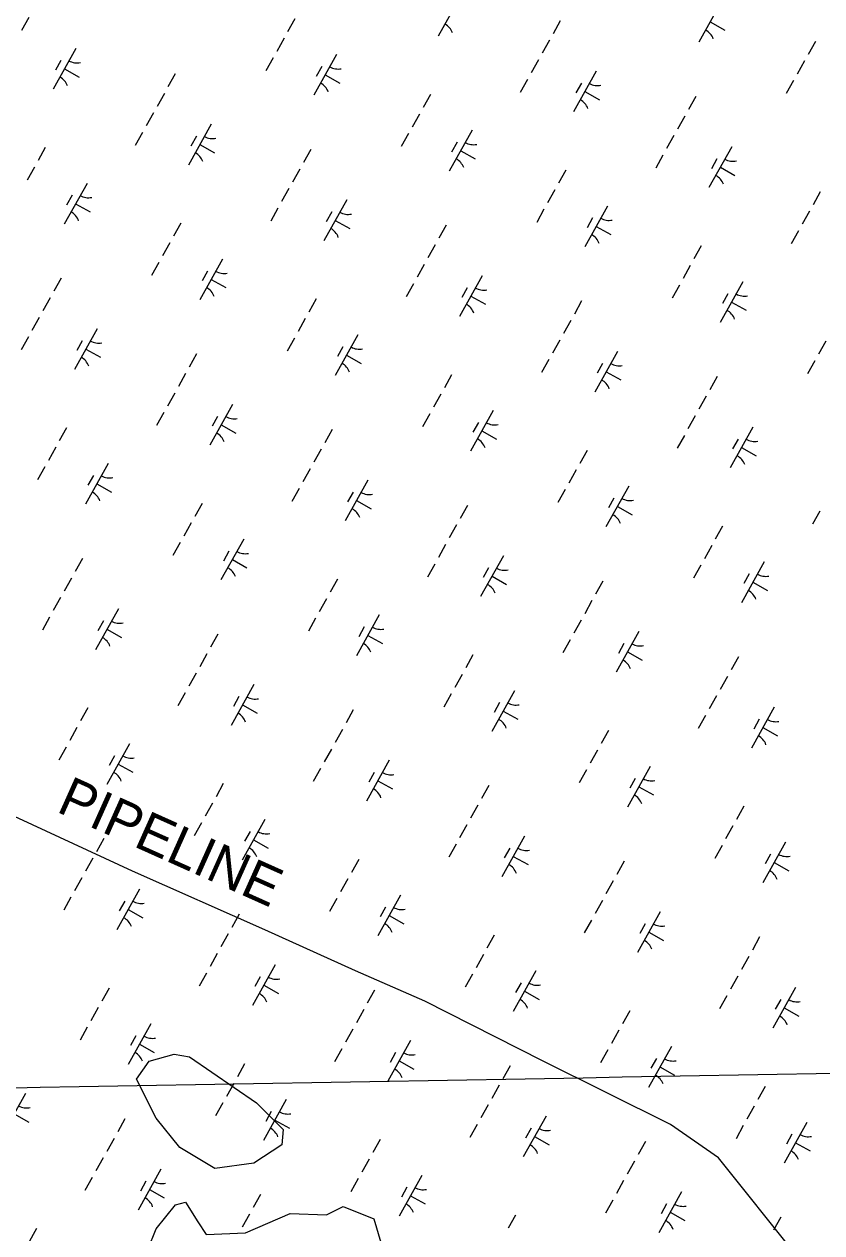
# Model space of a CAD drawing. Extents: x 3923531 to 3943530, y 207391 to 229799.
# Drawn here: x 3930894 to 3931749, y 217762 to 219057 of the extents above; entities that cross this region are included whole.
import ezdxf

# ---------------------------------------------------------------- set-up
doc = ezdxf.new("R2010")
doc.units = 0
for name, color, linetype in [('V-GRID-MAJR', 7, 'Continuous'), ('V-SITE-VEGE', 7, 'Continuous'), ('V-UTIL-IDEN', 7, 'Continuous'), ('V-UTIL-LINE', 7, 'Continuous'), ('V-WETL-SWMP', 7, 'Continuous')]:
    doc.layers.add(name, color=color, linetype=linetype)

msp = doc.modelspace()

# ---------------------------------------------------------------- linework, layer by layer
at = {"layer": 'V-GRID-MAJR'}
msp.add_spline([(3929435.5, 217891.9), (3930329.2, 217907.7), (3935652.4, 218002.6), (3939803.5, 218077.1)], degree=3, dxfattribs=at)
at = {"layer": 'V-SITE-VEGE'}
for points in [[(3931171.8, 217872.8), (3931170.3, 217856.3), (3931140.4, 217836.9), (3931098.5, 217830.9), (3931061.1, 217853.4), (3931035.6, 217884.8), (3931014.7, 217926.7), (3931028.2, 217946.2), (3931055.1, 217953.6), (3931071.6, 217950.6), (3931143.4, 217901.3)], [(3931179.3, 217783), (3931218.2, 217781.5), (3931236.1, 217790.5), (3931269, 217777), (3931276.5, 217751.6), (3931257.1, 217721.6), (3931239.1, 217693.2), (3931213.7, 217672.2), (3931176.3, 217663.3), (3931152.3, 217615.4), (3931116.4, 217598.9), (3931083.5, 217630.3), (3931055.1, 217673.7), (3931064.1, 217685.7), (3931089.5, 217690.2), (3931082, 217720.1), (3931041.6, 217723.1), (3931026.7, 217744.1), (3931035.6, 217766.5), (3931056.6, 217792), (3931067.1, 217795), (3931080.5, 217774), (3931089.5, 217760.5), (3931131.4, 217762)]]:
    msp.add_lwpolyline(points, close=True, dxfattribs=at)
at = {"layer": 'V-UTIL-LINE'}
msp.add_lwpolyline([(3931722.7, 217737.3), (3931638.5, 217842.4), (3931587.2, 217878.3), (3931450.1, 217946.4), (3931323.8, 218010.3), (3931249.5, 218042.8), (3931152.1, 218086.6), (3931010.3, 218149.6), (3930854.2, 218221.7), (3930697.7, 218316.3), (3930484, 218439.5), (3930190.1, 218598.9), (3929976.7, 218714), (3929898, 218757.3)], dxfattribs=at)
at = {"layer": 'V-WETL-SWMP'}
for p, q in [((3931362.4, 219087.9), (3931338, 219044.2)), ((3931642, 219081.4), (3931617.6, 219037.7)), ((3930899.3, 219064.2), (3930891.5, 219050.2)), ((3931184.5, 219062.9), (3931176.7, 219048.9)), ((3931469, 219060.8), (3931461.2, 219046.9)), ((3931629.8, 219059.6), (3931645.5, 219050.8)), ((3931172.8, 219042), (3931165, 219028)), ((3931457.3, 219039.9), (3931449.5, 219025.9)), ((3930949.6, 219031), (3930925.2, 218987.4)), ((3931742.5, 219038.6), (3931734.7, 219024.6)), ((3930933.6, 219018.2), (3930927.7, 219007.7)), ((3931161.1, 219021), (3931153.3, 219007)), ((3931229.2, 219024.5), (3931204.8, 218980.9)), ((3931445.6, 219018.9), (3931437.8, 219004.9)), ((3931730.8, 219017.7), (3931723, 219003.7)), ((3930937.4, 219009.2), (3930953.1, 219000.4)), ((3931056.2, 219004), (3931048.4, 218990)), ((3931213.2, 219011.7), (3931207.3, 219001.2)), ((3931217, 219002.7), (3931232.7, 218993.9)), ((3931507.6, 219006.7), (3931483.2, 218963.1)), ((3931433.9, 218998), (3931426.1, 218984)), ((3931491.6, 218993.9), (3931485.7, 218983.4)), ((3931719.1, 218996.7), (3931711.3, 218982.7)), ((3931044.5, 218983), (3931036.7, 218969.1)), ((3931329.7, 218981.8), (3931321.9, 218967.8)), ((3931495.4, 218984.9), (3931511.1, 218976.1)), ((3931614.3, 218979.7), (3931606.5, 218965.7)), ((3931032.8, 218962.1), (3931025, 218948.1)), ((3931094.8, 218949.9), (3931070.4, 218906.2)), ((3931318, 218960.8), (3931310.2, 218946.9)), ((3931602.6, 218958.7), (3931594.7, 218944.8)), ((3931021.1, 218941.1), (3931013.3, 218927.2)), ((3931078.8, 218937.1), (3931072.9, 218926.6)), ((3931306.3, 218939.9), (3931298.5, 218925.9)), ((3931374.4, 218943.4), (3931350, 218899.8)), ((3931590.8, 218937.8), (3931583, 218923.8)), ((3930916.9, 218924.9), (3930909.1, 218911)), ((3931082.6, 218928.1), (3931098.3, 218919.3)), ((3931358.4, 218930.6), (3931352.5, 218920.1)), ((3931652.8, 218925.6), (3931628.4, 218882)), ((3931201.4, 218922.9), (3931193.6, 218908.9)), ((3931362.2, 218921.6), (3931377.9, 218912.8)), ((3931579.1, 218916.8), (3931571.3, 218902.9)), ((3931636.8, 218912.8), (3931631, 218902.3)), ((3930905.2, 218904), (3930897.4, 218890)), ((3931189.7, 218901.9), (3931181.9, 218887.9)), ((3931474.9, 218900.7), (3931467.1, 218886.7)), ((3931640.6, 218903.8), (3931656.3, 218895)), ((3930961.6, 218886.6), (3930937.2, 218842.9)), ((3930945.6, 218873.8), (3930939.7, 218863.3)), ((3931178, 218881), (3931170.2, 218867)), ((3931463.2, 218879.7), (3931455.4, 218865.7)), ((3931747.8, 218877.6), (3931740, 218863.7)), ((3930949.4, 218864.8), (3930965.1, 218856)), ((3931166.3, 218860), (3931158.5, 218846)), ((3931240, 218868.8), (3931215.6, 218825.1)), ((3931451.5, 218858.8), (3931443.7, 218844.8)), ((3931519.6, 218862.3), (3931495.2, 218818.6)), ((3931224, 218855.9), (3931218.1, 218845.5)), ((3931227.8, 218846.9), (3931243.5, 218838.2)), ((3931503.6, 218849.5), (3931497.8, 218839)), ((3931736.1, 218856.7), (3931728.3, 218842.7)), ((3931062.1, 218843.8), (3931054.3, 218829.9)), ((3931346.6, 218841.7), (3931338.8, 218827.8)), ((3931507.4, 218840.5), (3931523.1, 218831.7)), ((3931724.4, 218835.7), (3931716.6, 218821.7)), ((3931050.4, 218822.9), (3931042.6, 218808.9)), ((3931334.9, 218820.8), (3931327.1, 218806.8)), ((3931620.1, 218819.5), (3931612.3, 218805.6)), ((3931038.7, 218801.9), (3931030.9, 218787.9)), ((3931106.8, 218805.5), (3931082.4, 218761.8)), ((3931323.2, 218799.8), (3931315.4, 218785.9)), ((3931608.4, 218798.6), (3931600.6, 218784.6)), ((3930933.8, 218784.9), (3930926, 218770.9)), ((3931090.8, 218792.6), (3931084.9, 218782.2)), ((3931094.6, 218783.6), (3931110.3, 218774.9)), ((3931385.2, 218787.6), (3931360.8, 218744)), ((3931664.8, 218781.2), (3931640.4, 218737.5)), ((3931311.5, 218778.9), (3931303.7, 218764.9)), ((3931369.2, 218774.8), (3931363.3, 218764.3)), ((3931596.7, 218777.6), (3931588.9, 218763.7)), ((3931648.8, 218768.3), (3931643, 218757.9)), ((3930922.1, 218763.9), (3930914.3, 218750)), ((3931207.3, 218762.7), (3931199.5, 218748.7)), ((3931373, 218765.8), (3931388.7, 218757)), ((3931491.9, 218760.6), (3931484.1, 218746.6)), ((3931652.6, 218759.3), (3931668.3, 218750.6)), ((3930910.4, 218743), (3930902.6, 218729)), ((3931195.6, 218741.7), (3931187.8, 218727.8)), ((3930972.4, 218730.8), (3930948, 218687.2)), ((3931480.2, 218739.7), (3931472.4, 218725.7)), ((3930898.7, 218722), (3930890.9, 218708.1)), ((3930956.4, 218718), (3930950.5, 218707.5)), ((3931183.9, 218720.8), (3931176.1, 218706.8)), ((3931252, 218724.3), (3931227.6, 218680.7)), ((3931468.5, 218718.7), (3931460.7, 218704.7)), ((3931753.6, 218717.5), (3931745.8, 218703.5)), ((3930960.2, 218709), (3930975.9, 218700.2)), ((3931079, 218703.8), (3931071.2, 218689.8)), ((3931236, 218711.5), (3931230.1, 218701)), ((3931530.4, 218706.5), (3931506, 218662.9)), ((3931239.8, 218702.5), (3931255.5, 218693.7)), ((3931456.7, 218697.8), (3931448.9, 218683.8)), ((3931514.4, 218693.7), (3931508.6, 218683.2)), ((3931741.9, 218696.5), (3931734.1, 218682.5)), ((3931067.3, 218682.8), (3931059.5, 218668.9)), ((3931352.5, 218681.6), (3931344.7, 218667.6)), ((3931518.2, 218684.7), (3931533.9, 218675.9)), ((3931637.1, 218679.5), (3931629.3, 218665.5)), ((3931055.6, 218661.9), (3931047.8, 218647.9)), ((3931340.8, 218660.6), (3931333, 218646.7)), ((3931625.4, 218658.5), (3931617.6, 218644.6)), ((3931043.9, 218640.9), (3931036.1, 218627)), ((3931117.6, 218649.7), (3931093.2, 218606)), ((3931329.1, 218639.7), (3931321.3, 218625.7)), ((3931397.2, 218643.2), (3931372.8, 218599.6)), ((3931101.6, 218636.9), (3931095.7, 218626.4)), ((3931105.4, 218627.9), (3931121.1, 218619.1)), ((3931381.2, 218630.4), (3931375.4, 218619.9)), ((3931613.7, 218637.6), (3931605.9, 218623.6)), ((3931675.6, 218625.4), (3931651.2, 218581.7)), ((3930939.7, 218624.7), (3930931.9, 218610.8)), ((3931224.3, 218622.7), (3931216.5, 218608.7)), ((3931385, 218621.4), (3931400.7, 218612.6)), ((3931602, 218616.6), (3931594.2, 218602.7)), ((3931659.6, 218612.6), (3931653.8, 218602.1)), ((3930928, 218603.8), (3930920.2, 218589.8)), ((3931212.6, 218601.7), (3931204.7, 218587.7)), ((3931497.7, 218600.4), (3931489.9, 218586.5)), ((3931663.4, 218603.6), (3931679.1, 218594.8)), ((3930984.4, 218586.4), (3930960, 218542.7)), ((3930916.3, 218582.8), (3930908.5, 218568.9)), ((3930968.4, 218573.5), (3930962.5, 218563.1)), ((3931200.8, 218580.7), (3931193, 218566.8)), ((3931486, 218579.5), (3931478.2, 218565.5)), ((3930972.2, 218564.5), (3930987.9, 218555.8)), ((3931262.8, 218568.6), (3931238.4, 218524.9)), ((3931542.4, 218562.1), (3931518, 218518.4)), ((3931189.1, 218559.8), (3931181.3, 218545.8)), ((3931246.8, 218555.7), (3931241, 218545.3)), ((3931474.3, 218558.5), (3931466.5, 218544.6)), ((3931526.4, 218549.3), (3931520.6, 218538.8)), ((3931084.9, 218543.6), (3931077.1, 218529.6)), ((3931250.6, 218546.7), (3931266.3, 218538)), ((3931369.5, 218541.5), (3931361.7, 218527.6)), ((3931530.2, 218540.3), (3931545.9, 218531.5)), ((3931747.2, 218535.5), (3931739.4, 218521.5)), ((3931073.2, 218522.7), (3931065.4, 218508.7)), ((3931357.8, 218520.6), (3931350, 218506.6)), ((3931643, 218519.3), (3931635.2, 218505.4)), ((3931061.5, 218501.7), (3931053.7, 218487.7)), ((3931129.6, 218505.2), (3931105.2, 218461.6)), ((3931346.1, 218499.6), (3931338.3, 218485.7)), ((3931631.3, 218498.4), (3931623.5, 218484.4)), ((3930956.7, 218484.7), (3930948.8, 218470.7)), ((3931113.6, 218492.4), (3931107.8, 218481.9)), ((3931117.4, 218483.4), (3931133.1, 218474.6)), ((3931408, 218487.4), (3931383.6, 218443.8)), ((3931334.4, 218478.7), (3931326.6, 218464.7)), ((3931392, 218474.6), (3931386.2, 218464.1)), ((3931619.6, 218477.4), (3931611.7, 218463.5)), ((3931687.6, 218481), (3931663.3, 218437.3)), ((3930944.9, 218463.7), (3930937.1, 218449.8)), ((3931230.1, 218462.5), (3931222.3, 218448.5)), ((3931395.8, 218465.6), (3931411.5, 218456.8)), ((3931514.7, 218460.4), (3931506.9, 218446.4)), ((3931671.6, 218468.1), (3931665.8, 218457.7)), ((3931675.4, 218459.1), (3931691.2, 218450.4)), ((3930933.2, 218442.8), (3930925.4, 218428.8)), ((3931218.4, 218441.5), (3931210.6, 218427.6)), ((3931503, 218439.5), (3931495.2, 218425.5)), ((3930921.5, 218421.8), (3930913.7, 218407.9)), ((3930995.2, 218430.6), (3930970.8, 218386.9)), ((3931206.7, 218420.6), (3931198.9, 218406.6)), ((3931274.8, 218424.1), (3931250.4, 218380.5)), ((3931491.3, 218418.5), (3931483.5, 218404.5)), ((3930979.2, 218417.8), (3930973.3, 218407.3)), ((3930983, 218408.8), (3930998.7, 218400)), ((3931258.8, 218411.3), (3931253, 218400.8)), ((3931553.2, 218406.3), (3931528.8, 218362.7)), ((3931101.9, 218403.6), (3931094.1, 218389.6)), ((3931262.6, 218402.3), (3931278.3, 218393.5)), ((3931479.6, 218397.5), (3931471.8, 218383.6)), ((3931537.2, 218393.5), (3931531.4, 218383)), ((3931090.2, 218382.6), (3931082.4, 218368.6)), ((3931375.4, 218381.4), (3931367.6, 218367.4)), ((3931541, 218384.5), (3931556.8, 218375.7)), ((3931659.9, 218379.3), (3931652.1, 218365.3)), ((3931078.5, 218361.7), (3931070.7, 218347.7)), ((3931363.7, 218360.4), (3931355.8, 218346.4)), ((3931648.2, 218358.3), (3931640.4, 218344.4)), ((3931066.7, 218340.7), (3931058.9, 218326.7)), ((3931140.4, 218349.5), (3931116, 218305.8)), ((3931420, 218343), (3931395.6, 218299.3)), ((3931124.4, 218336.7), (3931118.6, 218326.2)), ((3931128.2, 218327.7), (3931143.9, 218318.9)), ((3931351.9, 218339.5), (3931344.1, 218325.5)), ((3931404, 218330.2), (3931398.2, 218319.7)), ((3931636.5, 218337.4), (3931628.7, 218323.4)), ((3930962.5, 218324.5), (3930954.7, 218310.6)), ((3931247.1, 218322.4), (3931239.3, 218308.5)), ((3931407.8, 218321.2), (3931423.6, 218312.4)), ((3931624.8, 218316.4), (3931617, 218302.5)), ((3931698.4, 218325.2), (3931674.1, 218281.5)), ((3930950.8, 218303.6), (3930943, 218289.6)), ((3931235.4, 218301.5), (3931227.6, 218287.5)), ((3931682.4, 218312.4), (3931676.6, 218301.9)), ((3931686.3, 218303.4), (3931702, 218294.6)), ((3931520.6, 218300.2), (3931512.8, 218286.3)), ((3930939.1, 218282.6), (3930931.3, 218268.7)), ((3931007.2, 218286.2), (3930982.8, 218242.5)), ((3931223.7, 218280.5), (3931215.9, 218266.6)), ((3931508.9, 218279.3), (3931501.1, 218265.3)), ((3930991.2, 218273.3), (3930985.4, 218262.9)), ((3930995, 218264.3), (3931010.7, 218255.6)), ((3931285.6, 218268.4), (3931261.2, 218224.7)), ((3931212, 218259.6), (3931204.2, 218245.6)), ((3931269.6, 218255.5), (3931263.8, 218245.1)), ((3931497.2, 218258.3), (3931489.4, 218244.4)), ((3931565.2, 218261.9), (3931540.9, 218218.2)), ((3931107.7, 218243.4), (3931099.9, 218229.4)), ((3931273.4, 218246.5), (3931289.1, 218237.7)), ((3931392.3, 218241.3), (3931384.5, 218227.4)), ((3931549.2, 218249), (3931543.4, 218238.6)), ((3931553.1, 218240), (3931568.8, 218231.3)), ((3931096, 218222.5), (3931088.2, 218208.5)), ((3931380.6, 218220.4), (3931372.8, 218206.4)), ((3931665.8, 218219.1), (3931658, 218205.1)), ((3931084.3, 218201.5), (3931076.5, 218187.5)), ((3931152.4, 218205), (3931128, 218161.4)), ((3931368.9, 218199.4), (3931361.1, 218185.4)), ((3931654.1, 218198.2), (3931646.3, 218184.2)), ((3931136.4, 218192.2), (3931130.6, 218181.7)), ((3931430.8, 218187.2), (3931406.5, 218143.6)), ((3930979.5, 218184.5), (3930971.7, 218170.5)), ((3931140.2, 218183.2), (3931155.9, 218174.4)), ((3931357.2, 218178.5), (3931349.4, 218164.5)), ((3931414.8, 218174.4), (3931409, 218163.9)), ((3931642.4, 218177.2), (3931634.6, 218163.2)), ((3931710.5, 218180.7), (3931686.1, 218137.1)), ((3930967.8, 218163.5), (3930960, 218149.6)), ((3931253, 218162.3), (3931245.2, 218148.3)), ((3931418.6, 218165.4), (3931434.4, 218156.6)), ((3931537.5, 218160.2), (3931529.7, 218146.2)), ((3931694.5, 218167.9), (3931688.6, 218157.4)), ((3931698.3, 218158.9), (3931714, 218150.1)), ((3930956.1, 218142.6), (3930948.3, 218128.6)), ((3931241.3, 218141.3), (3931233.5, 218127.4)), ((3931525.8, 218139.2), (3931518, 218125.3)), ((3930944.4, 218121.6), (3930936.6, 218107.7)), ((3931018, 218130.4), (3930993.6, 218086.7)), ((3931229.6, 218120.4), (3931221.7, 218106.4)), ((3931297.6, 218123.9), (3931273.3, 218080.3)), ((3931002, 218117.6), (3930996.2, 218107.1)), ((3931005.8, 218108.6), (3931021.5, 218099.8)), ((3931281.6, 218111.1), (3931275.8, 218100.6)), ((3931514.1, 218118.3), (3931506.3, 218104.3)), ((3931124.7, 218103.4), (3931116.9, 218089.4)), ((3931285.4, 218102.1), (3931301.2, 218093.3)), ((3931502.4, 218097.3), (3931494.6, 218083.4)), ((3931576.1, 218106.1), (3931551.7, 218062.5)), ((3931113, 218082.4), (3931105.2, 218068.4)), ((3931398.2, 218081.2), (3931390.4, 218067.2)), ((3931560.1, 218093.3), (3931554.2, 218082.8)), ((3931563.9, 218084.3), (3931579.6, 218075.5)), ((3931682.7, 218079.1), (3931674.9, 218065.1)), ((3931101.3, 218061.5), (3931093.5, 218047.5)), ((3931386.5, 218060.2), (3931378.7, 218046.2)), ((3931671, 218058.1), (3931663.2, 218044.2)), ((3931163.2, 218049.3), (3931138.9, 218005.6)), ((3931442.9, 218042.8), (3931418.5, 217999.1)), ((3931089.6, 218040.5), (3931081.8, 218026.5)), ((3931147.2, 218036.4), (3931141.4, 218026)), ((3931374.8, 218039.3), (3931367, 218025.3)), ((3931426.9, 218030), (3931421, 218019.5)), ((3931659.3, 218037.2), (3931651.5, 218023.2)), ((3930985.4, 218024.3), (3930977.6, 218010.4)), ((3931151, 218027.4), (3931166.8, 218018.7)), ((3931269.9, 218022.2), (3931262.1, 218008.3)), ((3931430.7, 218021), (3931446.4, 218012.2)), ((3931721.3, 218025), (3931696.9, 217981.3)), ((3931647.6, 218016.2), (3931639.8, 218002.2)), ((3931705.3, 218012.2), (3931699.4, 218001.7)), ((3930973.7, 218003.4), (3930965.8, 217989.4)), ((3931258.2, 218001.3), (3931250.4, 217987.3)), ((3931543.4, 218000), (3931535.6, 217986.1)), ((3931709.1, 218003.2), (3931724.8, 217994.4)), ((3930961.9, 217982.4), (3930954.1, 217968.4)), ((3931030, 217986), (3931005.6, 217942.3)), ((3931246.5, 217980.3), (3931238.7, 217966.4)), ((3931531.7, 217979.1), (3931523.9, 217965.1)), ((3931014, 217973.1), (3931008.2, 217962.7)), ((3931308.4, 217968.1), (3931284.1, 217924.5)), ((3931017.8, 217964.1), (3931033.6, 217955.3)), ((3931234.8, 217959.4), (3931227, 217945.4)), ((3931292.4, 217955.3), (3931286.6, 217944.8)), ((3931520, 217958.1), (3931512.2, 217944.2)), ((3931588.1, 217961.7), (3931563.7, 217918)), ((3931130.6, 217943.2), (3931122.8, 217929.2)), ((3931296.3, 217946.3), (3931312, 217937.5)), ((3931415.1, 217941.1), (3931407.3, 217927.1)), ((3931572.1, 217948.8), (3931566.2, 217938.4)), ((3931575.9, 217939.8), (3931591.6, 217931.1)), ((3931118.9, 217922.2), (3931111.1, 217908.3)), ((3931403.4, 217920.2), (3931395.6, 217906.2)), ((3931688.6, 217918.9), (3931680.8, 217904.9)), ((3930895.6, 217911.3), (3930871.2, 217867.7)), ((3931107.2, 217901.3), (3931099.4, 217887.3)), ((3931175.2, 217904.8), (3931150.9, 217861.2)), ((3930883.4, 217889.5), (3930899.2, 217880.7)), ((3931159.2, 217892), (3931153.4, 217881.5)), ((3931391.7, 217899.2), (3931383.9, 217885.2)), ((3931453.7, 217887), (3931429.3, 217843.4)), ((3931676.9, 217898), (3931669.1, 217884)), ((3931002.3, 217884.3), (3930994.5, 217870.3)), ((3931163.1, 217883), (3931178.8, 217874.2)), ((3931380, 217878.3), (3931372.2, 217864.3)), ((3931437.7, 217874.2), (3931431.8, 217863.7)), ((3931665.2, 217877), (3931657.4, 217863)), ((3931733.3, 217880.5), (3931708.9, 217836.9)), ((3930990.6, 217863.3), (3930982.8, 217849.4)), ((3931275.8, 217862.1), (3931268, 217848.1)), ((3931441.5, 217865.2), (3931457.2, 217856.4)), ((3931717.3, 217867.7), (3931711.4, 217857.2)), ((3931560.3, 217860), (3931552.5, 217846)), ((3931721.1, 217858.7), (3931736.8, 217849.9)), ((3930978.9, 217842.4), (3930971.1, 217828.4)), ((3931264.1, 217841.1), (3931256.3, 217827.2)), ((3931548.6, 217839), (3931540.8, 217825.1)), ((3931040.8, 217830.2), (3931016.5, 217786.5)), ((3931320.5, 217823.7), (3931296.1, 217780.1)), ((3930967.2, 217821.4), (3930959.4, 217807.5)), ((3931024.8, 217817.4), (3931019, 217806.9)), ((3931252.4, 217820.2), (3931244.6, 217806.2)), ((3931304.5, 217810.9), (3931298.6, 217800.4)), ((3931536.9, 217818.1), (3931529.1, 217804.1)), ((3931028.7, 217808.4), (3931044.4, 217799.6)), ((3931147.5, 217803.2), (3931139.7, 217789.2)), ((3931308.3, 217801.9), (3931324, 217793.1)), ((3931525.2, 217797.1), (3931517.4, 217783.2)), ((3931598.9, 217805.9), (3931574.5, 217762.2)), ((3931582.9, 217793.1), (3931577, 217782.6)), ((3931586.7, 217784.1), (3931602.4, 217775.3)), ((3931135.8, 217782.2), (3931128, 217768.2)), ((3931421, 217780.9), (3931413.2, 217767)), ((3931705.5, 217778.9), (3931697.7, 217764.9)), ((3930907.6, 217766.9), (3930883.3, 217723.2))]:
    msp.add_line(p, q, dxfattribs=at)
for centre, start, end in [((3931336.9, 219041.8), 20.0381, 61.5817), ((3931616.5, 219035.3), 20.0381, 61.5817), ((3930951, 219033.2), 240.0381, 281.5817), ((3931230.7, 219026.7), 240.0381, 281.5817), ((3930924.1, 218985), 20.0381, 61.5817), ((3931203.7, 218978.5), 20.0381, 61.5817), ((3931509.1, 219008.9), 240.0381, 281.5817), ((3931482.1, 218960.7), 20.0381, 61.5817), ((3931096.3, 218952.1), 240.0381, 281.5817), ((3931375.9, 218945.6), 240.0381, 281.5817), ((3931069.3, 218903.8), 20.0381, 61.5817), ((3931348.9, 218897.4), 20.0381, 61.5817), ((3931654.3, 218927.8), 240.0381, 281.5817), ((3931627.3, 218879.6), 20.0381, 61.5817), ((3930963.1, 218888.8), 240.0381, 281.5817), ((3930936.1, 218840.5), 20.0381, 61.5817), ((3931241.5, 218870.9), 240.0381, 281.5817), ((3931521.1, 218864.5), 240.0381, 281.5817), ((3931214.5, 218822.7), 20.0381, 61.5817), ((3931494.1, 218816.2), 20.0381, 61.5817), ((3931108.3, 218807.6), 240.0381, 281.5817), ((3931081.3, 218759.4), 20.0381, 61.5817), ((3931386.7, 218789.8), 240.0381, 281.5817), ((3931666.3, 218783.3), 240.0381, 281.5817), ((3931359.7, 218741.6), 20.0381, 61.5817), ((3931639.4, 218735.1), 20.0381, 61.5817), ((3930973.9, 218733), 240.0381, 281.5817), ((3931253.5, 218726.5), 240.0381, 281.5817), ((3930946.9, 218684.8), 20.0381, 61.5817), ((3931226.5, 218678.3), 20.0381, 61.5817), ((3931531.9, 218708.7), 240.0381, 281.5817), ((3931505, 218660.5), 20.0381, 61.5817), ((3931119.1, 218651.9), 240.0381, 281.5817), ((3931398.7, 218645.4), 240.0381, 281.5817), ((3931092.1, 218603.6), 20.0381, 61.5817), ((3931371.8, 218597.2), 20.0381, 61.5817), ((3931677.1, 218627.6), 240.0381, 281.5817), ((3931650.2, 218579.3), 20.0381, 61.5817), ((3930985.9, 218588.5), 240.0381, 281.5817), ((3930958.9, 218540.3), 20.0381, 61.5817), ((3931264.3, 218570.7), 240.0381, 281.5817), ((3931543.9, 218564.3), 240.0381, 281.5817), ((3931237.4, 218522.5), 20.0381, 61.5817), ((3931517, 218516), 20.0381, 61.5817), ((3931131.1, 218507.4), 240.0381, 281.5817), ((3931104.1, 218459.2), 20.0381, 61.5817), ((3931409.5, 218489.6), 240.0381, 281.5817), ((3931382.6, 218441.4), 20.0381, 61.5817), ((3931689.1, 218483.1), 240.0381, 281.5817), ((3931662.2, 218434.9), 20.0381, 61.5817), ((3930996.7, 218432.8), 240.0381, 281.5817), ((3931276.3, 218426.3), 240.0381, 281.5817), ((3930969.7, 218384.5), 20.0381, 61.5817), ((3931249.4, 218378.1), 20.0381, 61.5817), ((3931554.7, 218408.5), 240.0381, 281.5817), ((3931527.8, 218360.3), 20.0381, 61.5817), ((3931141.9, 218351.6), 240.0381, 281.5817), ((3931421.5, 218345.2), 240.0381, 281.5817), ((3931115, 218303.4), 20.0381, 61.5817), ((3931394.6, 218296.9), 20.0381, 61.5817), ((3931699.9, 218327.4), 240.0381, 281.5817), ((3931673, 218279.1), 20.0381, 61.5817), ((3931008.7, 218288.3), 240.0381, 281.5817), ((3930981.8, 218240.1), 20.0381, 61.5817), ((3931287.1, 218270.5), 240.0381, 281.5817), ((3931260.2, 218222.3), 20.0381, 61.5817), ((3931566.7, 218264), 240.0381, 281.5817), ((3931539.8, 218215.8), 20.0381, 61.5817), ((3931153.9, 218207.2), 240.0381, 281.5817), ((3931127, 218159), 20.0381, 61.5817), ((3931432.3, 218189.4), 240.0381, 281.5817), ((3931711.9, 218182.9), 240.0381, 281.5817), ((3931405.4, 218141.2), 20.0381, 61.5817), ((3931685, 218134.7), 20.0381, 61.5817), ((3931019.5, 218132.6), 240.0381, 281.5817), ((3931299.1, 218126.1), 240.0381, 281.5817), ((3930992.6, 218084.3), 20.0381, 61.5817), ((3931272.2, 218077.9), 20.0381, 61.5817), ((3931577.5, 218108.3), 240.0381, 281.5817), ((3931550.6, 218060), 20.0381, 61.5817), ((3931164.7, 218051.4), 240.0381, 281.5817), ((3931444.3, 218045), 240.0381, 281.5817), ((3931137.8, 218003.2), 20.0381, 61.5817), ((3931417.4, 217996.7), 20.0381, 61.5817), ((3931722.8, 218027.2), 240.0381, 281.5817), ((3931695.8, 217978.9), 20.0381, 61.5817), ((3931031.5, 217988.1), 240.0381, 281.5817), ((3931004.6, 217939.9), 20.0381, 61.5817), ((3931309.9, 217970.3), 240.0381, 281.5817), ((3931589.6, 217963.8), 240.0381, 281.5817), ((3931283, 217922.1), 20.0381, 61.5817), ((3931562.6, 217915.6), 20.0381, 61.5817), ((3930897.1, 217913.5), 240.0381, 281.5817), ((3931176.7, 217907), 240.0381, 281.5817), ((3931149.8, 217858.8), 20.0381, 61.5817), ((3931455.1, 217889.2), 240.0381, 281.5817), ((3931734.8, 217882.7), 240.0381, 281.5817), ((3931428.2, 217841), 20.0381, 61.5817), ((3931707.8, 217834.5), 20.0381, 61.5817), ((3931042.3, 217832.4), 240.0381, 281.5817), ((3931321.9, 217825.9), 240.0381, 281.5817), ((3931015.4, 217784.1), 20.0381, 61.5817), ((3931295, 217777.7), 20.0381, 61.5817), ((3931600.4, 217808.1), 240.0381, 281.5817), ((3931573.4, 217759.8), 20.0381, 61.5817)]:
    msp.add_arc(centre, 17.6, start, end, dxfattribs=at)

# ---------------------------------------------------------------- texts
at = {"layer": 'V-UTIL-IDEN'}
msp.add_text('PIPELINE', height=42, rotation=335.8602, dxfattribs=at).set_placement((3930927.6, 218213.8))

doc.saveas('drawing.dxf')
